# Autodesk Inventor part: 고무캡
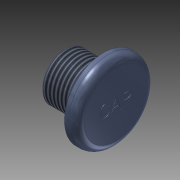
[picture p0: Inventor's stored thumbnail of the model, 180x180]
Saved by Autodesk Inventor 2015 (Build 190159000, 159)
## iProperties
Created: 2017-06
Part Number: 고무캡
Material: 고무
Document SubType Name: Modeling
Designer: mduedu
Density: 1 g/cm^3
Appearance: 고무 - 파란색 - 버전 1.1
Author: mduedu
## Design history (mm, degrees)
sketch "스케치1"
  geometry: L1 (0, 0)-(13, 0); L2 (13, 0)-(13, 10); L3 (13, 10)-(10, 10); L4 (0, 6)-(0, 0); L5 (0, 6)-(8, 6); L6 (8, 6)-(8, 8); L7 (8, 8)-(10, 8); L8 (10, 8)-(10, 10)
  constraints: 16 end point, 2 horizontal, 2 parallel, 2 perpendicular, 2 point on line, 1 vertical
  dimensions: "d0" = 20 diameter of L3 L1; "d2" = 12 diameter of L5 L1; "d6" = 5 distance between parallel lines of L2 L6; "d8" = 16 diameter of L7 L1; "d9" = 8 distance between parallel lines of L6 L4; "d32" = 2 distance of L6.end L7.end
revolve "회전1" sketch "스케치1" stored, may be unused: angle "d10" = 90 deg
hole "구멍1" diameter "d22" = 5; stored, may be unused: countersink angle "d26" = 90 deg, drill point angle "d28" = 0 deg; dims "d23" = 6, "d24" = 4, "d25" = 2, "d27" = 6, "d30" = 10, "d31" = 10
chamfer "모따기1" distance "d13" = 0.5; stored, may be unused: second distance "d14" = 2, angle "d15" = 45 deg
fillet "모깎기3" dims "d29" = 1
fillet "모깎기2" dims "d17" = 2
sketch "스케치3"
  geometry: 2 further points
  constraints: 1 coincident, 1 other
feature "엠보싱1" sketch "스케치3" dims "d18" = 0.2, "d19" = 0, "d29" = 1
feature "스레드1" dims "d33" = 10, "d34" = 0
node "솔리드1"
